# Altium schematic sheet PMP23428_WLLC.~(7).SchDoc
size 431 x 279 mm; Date: Not shown in title block; ApprovedBy: Not shown in title block; CheckedBy: Not shown in title block; Author: Not shown in title block; CompanyName: Not shown in title block; Engineer: Not shown in title block; Organization: Not shown in title block; Address1: Not shown in title block; Address2: Not shown in title block; Address3: Not shown in title block; Address4: Not shown in title block; DocumentNumber: 1; Revision: Use project parameter SCH_Rev; SheetNumber: 3; SheetTotal: 4; PageSetup: Record=PageOptions¦CenterHorizontal=True¦CenterVertical=True¦PrintScale=1.00¦XCorrection=1.00¦YCorrection=1.00¦PrintKind=0¦BorderSize=5000000¦LeftOffset=0¦BottomOffset=0¦Orientation=2¦PaperLength=1000¦PaperWidth=1000¦Scale=100¦PaperSource=15¦PrintQuality=600¦MediaType=1¦DitherType=10¦PaperKind=Letter¦PrintScaleMode=1
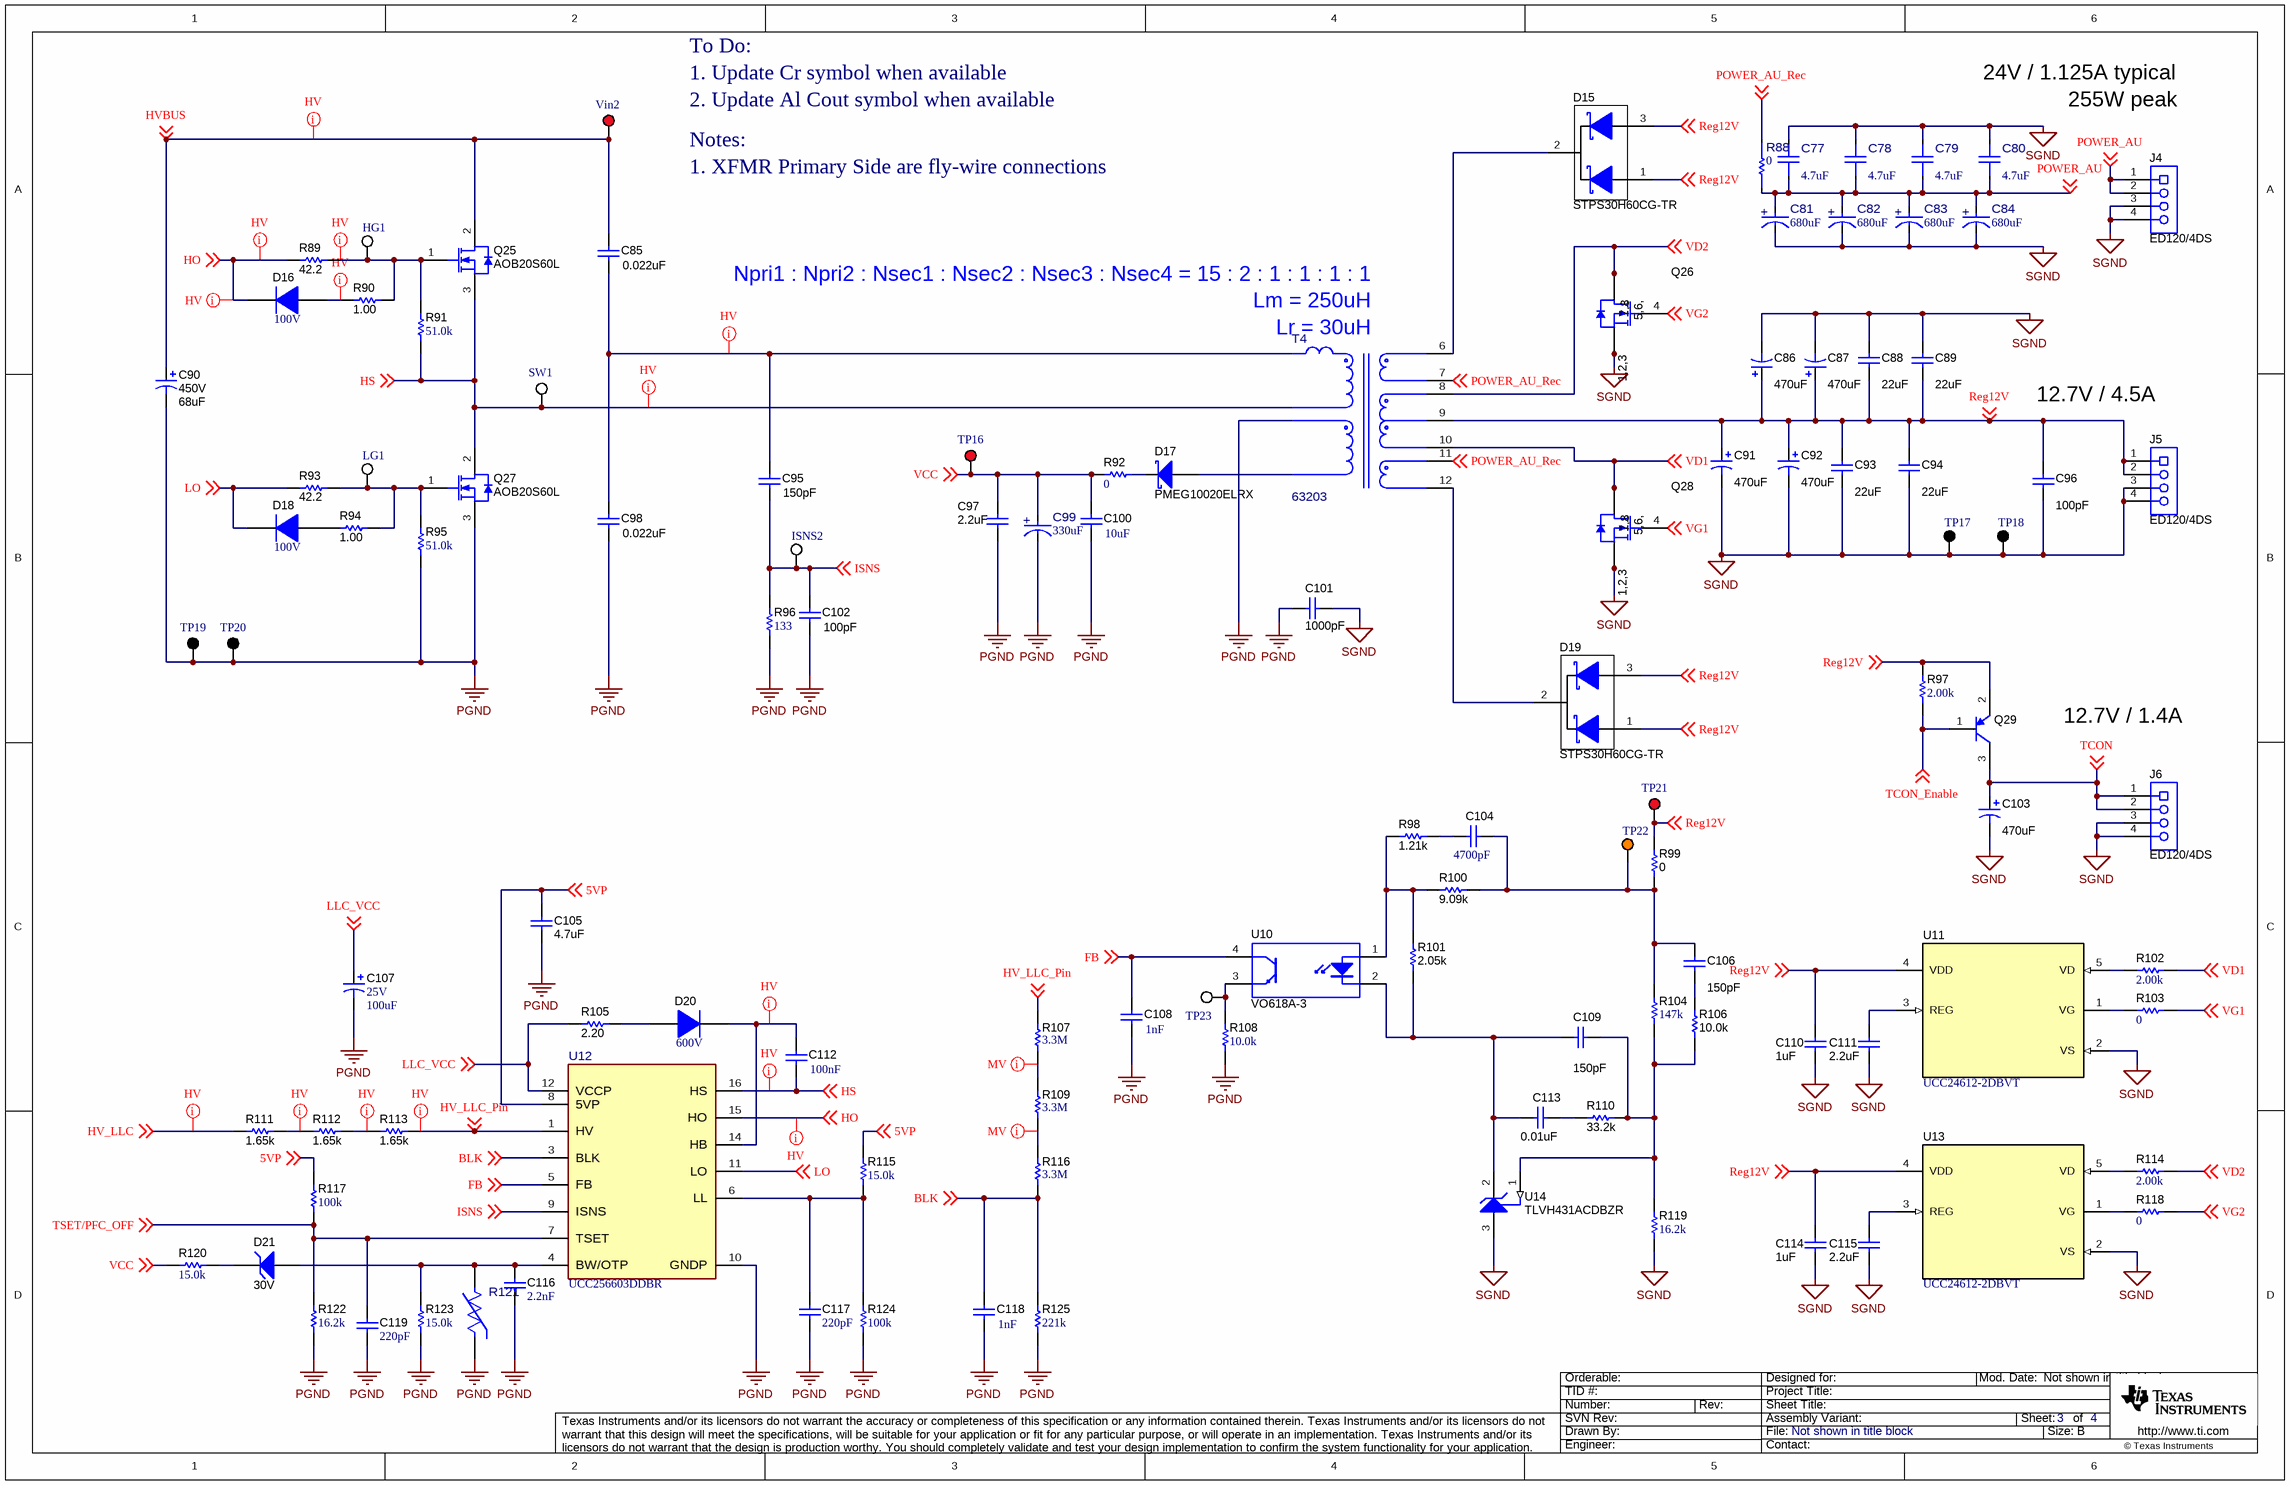
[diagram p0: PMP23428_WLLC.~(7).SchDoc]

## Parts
C77  ValueDisplayed: 4.7uF  [FP-885012208094_1206-MFG]  (hidden comment: 885012208094)
C78  ValueDisplayed: 4.7uF  [FP-885012208094_1206-MFG]  (hidden comment: 885012208094)
C79  ValueDisplayed: 4.7uF  [FP-885012208094_1206-MFG]  (hidden comment: 885012208094)
C80  ValueDisplayed: 4.7uF  [FP-885012208094_1206-MFG]  (hidden comment: 885012208094)
C81  ValueDisplayed: 680uF  [FP-EKZM350ELL681MJ25S_RADIAL-MFG]  (hidden comment: EKZM350ELL681MJ25S)
C82  ValueDisplayed: 680uF  [FP-EKZM350ELL681MJ25S_RADIAL-MFG]  (hidden comment: EKZM350ELL681MJ25S)
C83  ValueDisplayed: 680uF  [FP-EKZM350ELL681MJ25S_RADIAL-MFG]  (hidden comment: EKZM350ELL681MJ25S)
C84  ValueDisplayed: 680uF  [FP-EKZM350ELL681MJ25S_RADIAL-MFG]  (hidden comment: EKZM350ELL681MJ25S)
C85  ValueDisplayed: 0.022uF  [B32652_1800x700x1250]  (hidden comment: B32652A7153J000)
C86  ValueDisplayed: 470uF  [HW_1000x1600]  (hidden comment: UHW1V471MPD)
C87  ValueDisplayed: 470uF  [HW_1000x1600]  (hidden comment: UHW1V471MPD)
C88  ValueDisplayed: 22uF  [1206_190L]  (hidden comment: C3216X5R1E226M160AB)
C89  ValueDisplayed: 22uF  [1206_190L]  (hidden comment: C3216X5R1E226M160AB)
C90  VDC_V: 450V  ValueDisplayed: 68uF  [KXG_1800x3150]  (hidden comment: EKXG451ELL680MMN3S)
C91  ValueDisplayed: 470uF  [HW_1000x1600]  (hidden comment: UHW1V471MPD)
C92  ValueDisplayed: 470uF  [HW_1000x1600]  (hidden comment: UHW1V471MPD)
C93  ValueDisplayed: 22uF  [1206_190L]  (hidden comment: C3216X5R1E226M160AB)
C94  ValueDisplayed: 22uF  [1206_190L]  (hidden comment: C3216X5R1E226M160AB)
C95  ValueDisplayed: 150pF  [1206L]  (hidden comment: GRM31A5C2J151JW01D)
C96  ValueDisplayed: 100pF  [0603L]  (hidden comment: 06035A101FAT2A)
C97  ValueDisplayed: 2.2uF  [0805L]  (hidden comment: C2012X7R1V225K085AC)
C98  ValueDisplayed: 0.022uF  [B32652_1800x700x1250]  (hidden comment: B32652A7153J000)
C99  ValueDisplayed: 330uF  [FP-35ZL330MEFC10X16_RADIAL-MFG]  (hidden comment: 35ZL330MEFC10X16)
C100  ValueDisplayed: 10uF  [1210_270]  (hidden comment: GRM32ER6YA106KA12L)
C101  ValueDisplayed: 1000pF  [CD45_700x600x1100]  (hidden comment: CD45-E2GA102M-NKA)
C102  ValueDisplayed: 100pF  [1206L]  (hidden comment: 12061A101JAT2A)
C103  ValueDisplayed: 470uF  [HW_1000x1600]  (hidden comment: UHW1V471MPD)
C104  ValueDisplayed: 4700pF  [0603L]  (hidden comment: C0603C472J1GAC7867)
C105  ValueDisplayed: 4.7uF  [1206L]  (hidden comment: C3216X7R1E475K085AB)
C106  ValueDisplayed: 150pF  [0402L]  (hidden comment: 885012005062)
C107  VDC_V: 25V  ValueDisplayed: 100uF  [SM_RADIAL_E]  (hidden comment: EEE-FK1E101P)
C108  Cap_F: 1nF  [1206L]  (hidden comment: 12061A102JAT2A)
C109  ValueDisplayed: 150pF  [0402L]  (hidden comment: 885012005062)
C110  ValueDisplayed: 1uF  [0603L]  (hidden comment: GRM188R71C105KE15D)
C111  ValueDisplayed: 2.2uF  [0805L]  (hidden comment: C2012X7R1V225K085AC)
C112  Cap_F: 100nF  [1206_180L]  (hidden comment: GRM31C5C1E104JA01L)
C113  ValueDisplayed: 0.01uF  [0603L]  (hidden comment: 06031C103JAT2A)
C114  ValueDisplayed: 1uF  [0603L]  (hidden comment: GRM188R71C105KE15D)
C115  ValueDisplayed: 2.2uF  [0805L]  (hidden comment: C2012X7R1V225K085AC)
C116  Cap_F: 2.2nF  [0603]  (hidden comment: C0603X222K5RACTU)
C117  Cap_F: 220pF  [0603]  (hidden comment: C0603X221K5RACTU)
C118  Cap_F: 1nF  [0402L]  (hidden comment: 04025C102JAT2A)
C119  Cap_F: 220pF  [0603]  (hidden comment: C0603X221K5RACTU)
D15  STPS30H60CG-TR  [DDPAK]
D16  Vr_V: 100V  [SOD-123]  (hidden comment: 1N4148W-7-F)
D17  PMEG10020ELRX  [SOD-123W]
D18  Vr_V: 100V  [SOD-123]  (hidden comment: 1N4148W-7-F)
D19  STPS30H60CG-TR  [DDPAK]
D20  Vr_V: 600V  [SMAF]  (hidden comment: ES1JAF)
D21  value 30V  [SMA]  (hidden comment: SMAZ30-13-F)
HG1  5012  [Keystone5012]  (value not drawn)
ISNS2  5012  [Keystone5012]  (value not drawn)
J4  ED120/4DS  [On-Shore_ED120_4DS]
J5  ED120/4DS  [On-Shore_ED120_4DS]
J6  ED120/4DS  [On-Shore_ED120_4DS]
LG1  5012  [Keystone5012]  (value not drawn)
Q25  AOB20S60L  [DDPAK]
Q26  CSD19502Q5B  [DNK0008A]  (value not drawn)
Q27  AOB20S60L  [DDPAK]
Q28  CSD19502Q5B  [DNK0008A]  (value not drawn)
Q29  ZXTP25040DFHTA  [SOT-23]  (value not drawn)
R88  value 0  [FP-RMCF1206ZT0R00_1206-MFG]  (hidden comment: RMCF1206ZT0R00)
R89  ValueDisplayed: 42.2  [0603]  (hidden comment: RC0603FR-0742R2L)
R90  ValueDisplayed: 1.00  [0603L]  (hidden comment: RC0603FR-071RL)
R91  ValueDisplayed: 51.0k  [0603L]  (hidden comment: RC0603FR-0751KL)
R92  ValueDisplayed: 0  [1206L]  (hidden comment: ERJ-8GEY0R00V)
R93  ValueDisplayed: 42.2  [0603L]  (hidden comment: RC0603FR-0742R2L)
R94  ValueDisplayed: 1.00  [0603L]  (hidden comment: RC0603FR-071RL)
R95  ValueDisplayed: 51.0k  [0603L]  (hidden comment: RC0603FR-0751KL)
R96  ValueDisplayed: 133  [1206]  (hidden comment: RC1206FR-07133RL)
R97  ValueDisplayed: 2.00k  [0603]  (hidden comment: RC0603FR-072KL)
R98  ValueDisplayed: 1.21k  [0603L]  (hidden comment: RC0603FR-071K21L)
R99  ValueDisplayed: 0  [0402L]  (hidden comment: RC0402JR-070RL)
R100  ValueDisplayed: 9.09k  [0603L]  (hidden comment: RC0603FR-079K09L)
R101  ValueDisplayed: 2.05k  [0603L]  (hidden comment: RC0603FR-072K05L)
R102  ValueDisplayed: 2.00k  [0603]  (hidden comment: RC0603FR-072KL)
R103  ValueDisplayed: 0  [0603L]  (hidden comment: RC0603JR-070RL)
R104  ValueDisplayed: 147k  [0603L]  (hidden comment: RC0603FR-07147KL)
R105  ValueDisplayed: 2.20  [0603L]  (hidden comment: ERJ-3RQF2R2V)
R106  ValueDisplayed: 10.0k  [0603L]  (hidden comment: ERJ-3EKF1002V)
R107  Res_ohm: 3.3M  [FP-KTR18EZPF3304_1206-MFG]  (hidden comment: KTR18EZPF3304)
R108  ValueDisplayed: 10.0k  [0402L]  (hidden comment: ERJ-2RKF1002X)
R109  Res_ohm: 3.3M  [FP-KTR18EZPF3304_1206-MFG]  (hidden comment: KTR18EZPF3304)
R110  ValueDisplayed: 33.2k  [0603L]  (hidden comment: RC0603FR-0733K2L)
R111  ValueDisplayed: 1.65k  [1206L]  (hidden comment: CRCW12061K65FKEA)
R112  ValueDisplayed: 1.65k  [1206L]  (hidden comment: CRCW12061K65FKEA)
R113  ValueDisplayed: 1.65k  [1206L]  (hidden comment: CRCW12061K65FKEA)
R114  ValueDisplayed: 2.00k  [0603]  (hidden comment: RC0603FR-072KL)
R115  ValueDisplayed: 15.0k  [0603]  (hidden comment: RT0603BRD0715KL)
R116  Res_ohm: 3.3M  [FP-KTR18EZPF3304_1206-MFG]  (hidden comment: KTR18EZPF3304)
R117  ValueDisplayed: 100k  [0603]  (hidden comment: RC0603FR-07100KL)
R118  ValueDisplayed: 0  [0603L]  (hidden comment: RC0603JR-070RL)
R119  ValueDisplayed: 16.2k  [0603]  (hidden comment: RC0603FR-0716K2L)
R120  ValueDisplayed: 15.0k  [0603]  (hidden comment: RG1608P-153-B-T5)
R121  B57371V2474J060  [FP-B57371V2474J060_0603-MFG]  (value not drawn)
R122  ValueDisplayed: 16.2k  [0603]  (hidden comment: RC0603FR-0716K2L)
R123  ValueDisplayed: 15.0k  [0603]  (hidden comment: RG1608P-153-B-T5)
R124  ValueDisplayed: 100k  [0603]  (hidden comment: RT0603BRD07100KL)
R125  ValueDisplayed: 221k  [0603]  (hidden comment: RC0603FR-07221KL)
SW1  5012  [Keystone5012]  (value not drawn)
T4  63203  [FP-63203_W80MM0_H64MM0-MFG]
TP16  5010  [Keystone5010]  (value not drawn)
TP17  5011  [Keystone5011]  (value not drawn)
TP18  5011  [Keystone5011]  (value not drawn)
TP19  5011  [Keystone5011]  (value not drawn)
TP20  5011  [Keystone5011]  (value not drawn)
TP21  5010  [Keystone5010]  (value not drawn)
TP22  5013  [Keystone5013]  (value not drawn)
TP23  5012  [Keystone5012]  (value not drawn)
U10  VO618A-3  [DIP-4]
U11  UCC24612-2DBVT  [DBV0005A_N]
U12  UCC256603DDBR  [DDB0014A-MFG]
U13  UCC24612-2DBVT  [DBV0005A_N]
U14  TLVH431ACDBZR  [DBZ0003A_N]
Vin2  5010  [Keystone5010]  (value not drawn)

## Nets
PGND: C90.2(-) C97.2 C98.2 C99.1(CATHODE) C100.2 C101.2 C102.2 C105.2 C107.2(-) C108.2 C116.2 C117.2 C118.2 C119.2 Q27.3(S) R95.1 R96.1 R108.1 R121.1 R122.1 R123.1 R124.1 R125.1 TP19.1 TP20.1 U12.10(GNDP)
SGND: C77.2 C78.2 C79.2 C80.2 C81.1(CATHODE) C82.1(CATHODE) C83.1(CATHODE) C84.1(CATHODE) C86.2(-) C87.2(-) C88.1 C89.1 C91.2(-) C92.2(-) C93.2 C94.2 C96.2 C101.1 C103.2(-) C110.2 C111.2 C114.2 C115.2 J4.3 J4.4 J5.3 J5.4 J6.3 J6.4 Q26.1(S) Q26.2(S) Q26.3(S) Q28.1(S) Q28.2(S) Q28.3(S) R119.1 TP17.1 TP18.1 U11.2(VS) U13.2(VS) U14.3(ANODE)
5VP: C105.1 R115.2 R117.2 U12.8(5VP) ; off-sheet 5VP
BLK: C118.1 R116.1 R125.2 U12.3(BLK) ; off-sheet BLK
FB: C108.1 U10.4(C) U12.5(FB) ; off-sheet FB
HO: D16.1(K) R89.1 U12.15(HO) ; off-sheet HO
HS: C112.2 Q25.3(S) Q27.2(D) R91.1 SW1.1 U12.16(HS) ; off-sheet HS
HV_LLC: R111.1 ; off-sheet HV_LLC
HV_LLC_Pin: R107.2 R113.2 U12.1(HV) ; off-sheet HV_LLC_Pin
HVBUS: C85.1 C90.1(+) Q25.2(D) Vin2.1 ; off-sheet HVBUS
ISNS: C95.2 C102.1 ISNS2.1 R96.2 U12.9(ISNS) ; off-sheet ISNS
LLC_VCC: C107.1(+) R105.1 U12.12(VCCP) ; off-sheet LLC_VCC
LO: D18.1(K) R93.1 U12.11(LO) ; off-sheet LO
POWER_AU: C77.1 C78.1 C79.1 C80.1 C81.2(ANODE) C82.2(ANODE) C83.2(ANODE) C84.2(ANODE) J4.1 J4.2 R88.2 ; off-sheet POWER_AU
POWER_AU_Rec: R88.1 T4.7 T4.11 ; off-sheet POWER_AU_Rec
Reg12V: C86.1(+) C87.1(+) C88.2 C89.2 C91.1(+) C92.1(+) C93.1 C94.1 C96.1 C110.1 C114.1 D15.1(A) D15.3(A) D19.1(A) D19.3(A) J5.1 J5.2 Q29.2(E) R97.2 R99.2 T4.9 TP21.1 U11.4(VDD) U13.4(VDD) ; off-sheet Reg12V
TCON: C103.1(+) J6.1 J6.2 Q29.3(C) ; off-sheet TCON
TCON_Enable: Q29.1(B) R97.1 ; off-sheet TCON_Enable
TSET/PFC_OFF: C119.1 R117.1 R122.2 U12.7(TSET) ; off-sheet TSET/PFC_OFF
VCC: C97.1 C99.2(ANODE) C100.1 R92.1 R120.2 TP16.1 ; off-sheet VCC
VD1: Q28.5(D) Q28.6(D) Q28.7(D) Q28.8(D) Q28.9(D) R102.2 T4.10 ; off-sheet VD1
VD2: Q26.5(D) Q26.6(D) Q26.7(D) Q26.8(D) Q26.9(D) R114.2 T4.8 ; off-sheet VD2
VG1: Q28.4(G) R103.1 ; off-sheet VG1
VG2: Q26.4(G) R118.1 ; off-sheet VG2
NetC85_2: C85.2 C95.1 C98.1
NetC104_1: C104.1 C106.1 R99.1 R100.2 R104.2 TP22.1
NetC104_2: C104.2 R98.2
NetC106_2: C106.2 R106.2
NetC109_1: C109.1 R104.1 R106.1 R110.1 R119.2 U14.1(REF)
NetC109_2: C109.2 C113.2 R101.1 U10.2(K) U14.2(CATHODE)
NetC111_1: C111.1 U11.3(REG)
NetC112_1: C112.1 D20.1(K) U12.14(HB)
NetC113_1: C113.1 R110.2
NetC115_1: C115.1 U13.3(REG)
NetC116_1: C116.1 D21.2(A) R121.2 R123.2 U12.4(BW/OTP)
NetC117_1: C117.1 R115.1 R124.2 U12.6(LL)
NetD15_2: D15.2(K) T4.6
NetD16_2: D16.2(A) R90.1
NetD17_1: D17.1(K) R92.2
NetD18_2: D18.2(A) R94.1
NetD19_2: D19.2(K) T4.12
NetD20_2: D20.2(A) R105.2
NetD21_1: D21.1(K) R120.1
NetHG1_1: HG1.1 Q25.1(G) R89.2 R90.2 R91.2
NetLG1_1: LG1.1 Q27.1(G) R93.2 R94.2 R95.2
NetR98_1: R98.1 R100.1 R101.2 U10.1(A)
NetR102_1: R102.1 U11.5(VD)
NetR103_2: R103.2 U11.1(VG)
NetR107_1: R107.1 R109.2
NetR108_2: R108.2 TP23.1 U10.3(E)
NetR109_1: R109.1 R116.2
NetR111_2: R111.2 R112.1
NetR112_2: R112.2 R113.1
NetR114_1: R114.1 U13.5(VD)
NetR118_2: R118.2 U13.1(VG)

Not connected (* = marked no-connect by the designer): D17 2(A)

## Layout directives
net class HV: HO, HS, HV_LLC, HV_LLC_Pin, HVBUS, NetC85_2, NetC112_1, NetD16_2, NetHG1_1, NetR111_2, NetR112_2
net class MV: NetR107_1, NetR109_1

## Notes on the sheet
- To Do:
- 1. Update Cr symbol when available
- 255W peak
- 24V / 1.125A typical
- 2. Update Al Cout symbol when available
- Notes:
- 1. XFMR Primary Side are fly-wire connections
- Lm = 250uH
- (near C85) Npri1 : Npri2 : Nsec1 : Nsec2 : Nsec3 : Nsec4 = 15 : 2 : 1 : 1 : 1 : 1
- Lr = 30uH
- 12.7V / 4.5A
- 12.7V / 1.4A

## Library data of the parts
C77-C80 = CMP-0088282-2: 4.7µF ±10% 50V Ceramic Capacitor X7R 1206 (3216 Metric); Manufacturer: Wurth Electronics; TempCo: 15%; Symbol Name: SYM-885012208094; SizeZ_mm: 1.9mm; AEC Qualified: No
C81-C84 = CMP-0001423-1: Cap Aluminum Lytic 680uF 35V 20% (10 X 25mm) Radial 5mm 2250mA 10000h 105 Bulk; Manufacturer: United Chemi-Con; AEC Qualified: No; Cap_F: 680µF; IRMS_A: 2.25A; SizeZ_mm: 26.5mm; Dissipation Factor: 12%; Leakage Current: 238uA; Life: 10000Hours; Value: 680µF
C85 C98 = CMP-0012346-3: Manufacturer: TDK; TaMin_C: -55°C; Polarized: N; SizeAreaWB_mm2: 180; Value1: Unknown; Value: 0.015uF; TaMax_C: 100°C; Tolerance_%: 5%; SizeZ_mm: 12.5; SizeX_mm: 18; SizeY_mm: 7; Cap_Case: 18x7x12.5; Value2: 1250V; SizeArea_mm2: 126; CompType: Capacitor; AEC Qualified: Y; Cap_F: 15nF; VDC_V: 1.25kV; AEC Grade: 3; AEC Category: Q200
C86 C87 C91 C92 C103 = CMP-0010541-2: CAP, AL, 470 uF, 35 V, +/- 20%, 0.03 ohm, TH; Manufacturer: Nichicon; TaMin_C: -40°C; ESR_ohm: 0.03; Polarized: Y; SizeAreaWB_mm2: 144; U/M: EA; Value: 470uF; TaMax_C: 105°C; SizeZ_mm: 17.5; SizeX_mm: 10; Cap_Case: 10x16mm; Value2: 35V; SizeArea_mm2: 100; CompType: Capacitor; AEC Qualified: N; Cap_F: 470µF; IRMS_A: 2A; AEC Category: Q200
C88 C89 C93 C94 = CMP-0008654-2: CAP, CERM, 22 uF, 25 V, +/- 20%, X5R, 1206_190; Manufacturer: TDK; TaMin_C: -55°C; Polarized: N; SizeAreaWB_mm2: 10.92; Value1: Unknown; U/M: EA; Value: 22uF; TaMax_C: 85°C; SizeZ_mm: 1.9; SizeX_mm: 3.2; SizeY_mm: 1.6; Cap_Case: 1206; Value2: 25V; SizeArea_mm2: 5.12; CompType: Capacitor; Cap_F: 22µF; AEC Category: Q200
C90 = CMP-0010043-2: CAP, AL, 68 uF, 450 V, +/- 20%, TH; Manufacturer: Chemi-Con; TaMin_C: -25°C; Polarized: Y; SizeAreaWB_mm2: 400; Value1: Unknown; U/M: EA; Value: 68uF; TaMax_C: 105°C; SizeZ_mm: 33; SizeX_mm: 18; Cap_Case: 18x31.5mm; SizeArea_mm2: 324; CompType: Capacitor; Cap_F: 68µF; IRMS_A: 6.3dA; AEC Category: Q200
C95 = CMP-0008885-2: CAP, CERM, 150 pF, 630 V, +/- 5%, C0G/NP0, 1206; Manufacturer: MuRata; TaMin_C: -55°C; Polarized: N; SizeAreaWB_mm2: 10.92; Value1: Unknown; U/M: EA; Value: 150pF; TaMax_C: 125°C; SizeZ_mm: 1.35; SizeX_mm: 3.2; SizeY_mm: 1.6; Cap_Case: 1206; Value2: 630V; SizeArea_mm2: 5.12; CompType: Capacitor; AEC Category: Q200
C96 = CMP-0006762-4: CAP, CERM, 100 pF, 50 V, +/- 1%, C0G/NP0, 0603; Manufacturer: AVX; TaMin_C: -55°C; Polarized: N; SizeAreaWB_mm2: 4.68; Value1: Unknown; U/M: EA; TaMax_C: 125°C; SizeZ_mm: 1; SizeX_mm: 1.6; SizeY_mm: 0.8; Cap_Case: 0603; Value2: 50V; SizeArea_mm2: 1.28; CompType: Capacitor; Value: 100pF; AEC Category: Q200
C97 C111 C115 = CMP-0007883-2: CAP, CERM, 2.2 uF, 35 V, +/- 10%, X7R, 0805; Manufacturer: TDK; TaMin_C: -55°C; Polarized: N; SizeAreaWB_mm2: 6.75; Value1: Unknown; U/M: EA; Value: 2.2uF; TaMax_C: 125°C; SizeZ_mm: 1.45; SizeX_mm: 2; SizeY_mm: 1.25; Cap_Case: 0805; Value2: 35V; SizeArea_mm2: 2.5; CompType: Capacitor; Cap_F: 2.2µF; AEC Category: Q200
C99 = CMP-0098283-1: Cap Aluminum Lytic 330uF 35V 20% (10 X 16mm) Radial 5mm 1430mA 4000h 105C Bulk; Manufacturer: Rubycon; AEC Qualified: No; Cap_F: 330µF; IRMS_A: 1.43A; SizeZ_mm: 17.5mm; Dissipation Factor: 12%; Leakage Current: 115.5uA; Life: 4000Hours; Value: 330µF
C100 = CMP-0009215-2: CAP, CERM, 10 uF, 35 V, +/- 10%, X5R, 1210; Manufacturer: MuRata; TaMin_C: -55°C; Polarized: N; SizeAreaWB_mm2: 14.7; Value1: Unknown; U/M: EA; Value: 10uF; TaMax_C: 85°C; SizeZ_mm: 2.7; SizeX_mm: 3.2; SizeY_mm: 2.5; Cap_Case: 1210; Value2: 35V; SizeArea_mm2: 8; Cap_F: 10µF; AEC Category: Q200
C101 = CMP-0009595-2: CAP, CERM, 1000 pF,  V, +/- 20%, E, D7xT6mm; Manufacturer: TDK; TaMin_C: -25°C; Polarized: N; SizeAreaWB_mm2: 101.2; Value1: Unknown; U/M: EA; Value: 1000pF; TaMax_C: 125°C; SizeZ_mm: 11; SizeX_mm: 10.65; SizeY_mm: 6; Cap_Case: 7x6x11mm; SizeArea_mm2: 63.9; Cap_F: 1nF; AEC Category: Q200
C102 = CMP-0008462-2: CAP, CERM, 100 pF, 100 V, +/- 5%, C0G/NP0, 1206; Manufacturer: AVX; TaMin_C: -55°C; ESR_ohm: 7.01d; Polarized: N; SizeAreaWB_mm2: 10.92; Value1: 0.701 ohm; U/M: EA; Value: 100pF; TaMax_C: 125°C; SizeZ_mm: 1.35; SizeX_mm: 3.2; SizeY_mm: 1.6; Cap_Case: 1206; Value2: 100V; SizeArea_mm2: 5.12; CompType: Capacitor; AEC Category: Q200
C104 = CMP-0006941-4: CAP, CERM, 4700 pF, 100 V, +/- 5%, C0G/NP0, 0603; Manufacturer: Kemet; TaMin_C: -55°C; Polarized: N; SizeAreaWB_mm2: 4.68; Value1: Unknown; U/M: EA; Value: 4700pF; TaMax_C: 125°C; SizeZ_mm: 1; SizeX_mm: 1.6; SizeY_mm: 0.8; Cap_Case: 0603; Value2: 100V; SizeArea_mm2: 1.28; Cap_F: 4.7nF; AEC Category: Q200
C105 = CMP-0008693-2: CAP, CERM, 4.7 uF, 25 V, +/- 10%, X7R, 1206; Manufacturer: TDK; TaMin_C: -55°C; Polarized: N; SizeAreaWB_mm2: 10.92; Value1: Unknown; U/M: EA; Value: 4.7uF; TaMax_C: 125°C; SizeZ_mm: 1.35; SizeX_mm: 3.2; SizeY_mm: 1.6; Cap_Case: 1206; Value2: 25V; SizeArea_mm2: 5.12; CompType: Capacitor; Cap_F: 4.7µF; AEC Category: Q200
C106 C109 = CMP-0064913-2: CAP, CERM, 150 pF, 50 V,+/- 5%, C0G/NP0, 0402; Manufacturer: Wurth Elektronik; TaMin_C: -55°C; Polarized: N; SizeAreaWB_mm2: 3; Value1: Unknown; U/M: EA; Value: 150pF; TaMax_C: 125°C; SizeZ_mm: 0.6; SizeX_mm: 1; SizeY_mm: 0.5; Cap_Case: 0402; Value2: 50V; CompType: Capacitor; AEC Category: Q200
C107 = CMP-0010710-1: CAP, AL, 100 uF, 25 V, +/- 20%, 0.26 ohm, AEC-Q200 Grade 2, SMD; Manufacturer: Panasonic; TaMin_C: -55°C; ESR_ohm: 2.6d; Polarized: Y; SizeAreaWB_mm2: 118.45; U/M: EA; Value: 100uF; TaMax_C: 105°C; SizeZ_mm: 6.2; SizeX_mm: 9.5; SizeY_mm: 8.3; Cap_Case: E; SizeArea_mm2: 78.85; CompType: Capacitor; Cap_F: 100µF; IRMS_A: 3dA; AEC Grade: 2; AEC Category: Q200
C108 = CMP-0008465-2: CAP, CERM, 1000 pF, 100 V, +/- 5%, C0G/NP0, 1206; Manufacturer: AVX; TaMin_C: -55°C; ESR_ohm: 2.38d; Polarized: N; SizeAreaWB_mm2: 10.92; Value1: 0.238 ohm; U/M: EA; Value: 1000pF; TaMax_C: 125°C; SizeZ_mm: 1.35; SizeX_mm: 3.2; SizeY_mm: 1.6; Cap_Case: 1206; Value2: 100V; SizeArea_mm2: 5.12; AEC Category: Q200
C110 C114 = CMP-0007380-4: CAP, CERM, 1 uF, 16 V, +/- 10%, X7R, 0603; Manufacturer: MuRata; TaMin_C: -55°C; Polarized: N; SizeAreaWB_mm2: 4.68; Value1: Unknown; U/M: EA; Value: 1uF; TaMax_C: 125°C; SizeZ_mm: 1; SizeX_mm: 1.6; SizeY_mm: 0.8; Cap_Case: 0603; Value2: 16V; SizeArea_mm2: 1.28; CompType: Capacitor; Cap_F: 1µF; AEC Category: Q200
C112 = CMP-0064950-2: CAP, CERM, 0.1 uF, 25 V,+/- 5%, C0G/NP0, 1206; Manufacturer: MuRata; TaMin_C: -55°C; Polarized: N; SizeAreaWB_mm2: 10.92; Value1: Unknown; U/M: EA; Value: 0.1uF; TaMax_C: 125°C; SizeZ_mm: 1.8; SizeX_mm: 3.2; SizeY_mm: 1.6; Cap_Case: 1206; Value2: 25V; SizeArea_mm2: 5.12; AEC Category: Q200
C113 = CMP-0006726-4: CAP, CERM, 0.01 uF, 100 V, +/- 5%, X7R, 0603; Manufacturer: AVX; TaMin_C: -55°C; ESR_ohm: 0.098; Polarized: N; SizeAreaWB_mm2: 4.68; Value1: 0.098 ohm; U/M: EA; Value: 0.01uF; TaMax_C: 125°C; SizeZ_mm: 1; SizeX_mm: 1.6; SizeY_mm: 0.8; Cap_Case: 0603; Value2: 100V; SizeArea_mm2: 1.28; Cap_F: 10nF; AEC Category: Q200
C116 = CMP-0006983-4: CAP, CERM, 2200 pF, 50 V, +/- 10%, X7R, 0603; Manufacturer: Kemet; TaMin_C: -55°C; Polarized: N; SizeAreaWB_mm2: 4.68; Value1: Unknown; U/M: EA; Value: 2200pF; TaMax_C: 125°C; SizeZ_mm: 1; SizeX_mm: 1.6; SizeY_mm: 0.8; Value2: 50V; SizeArea_mm2: 1.28; AEC Category: Q200
C117 C119 = CMP-0006982-4: CAP, CERM, 220 pF, 50 V, +/- 10%, X7R, 0603; Manufacturer: Kemet; TaMin_C: -55°C; Polarized: N; SizeAreaWB_mm2: 4.68; Value1: Unknown; U/M: EA; Value: 220pF; TaMax_C: 125°C; SizeZ_mm: 1; SizeX_mm: 1.6; SizeY_mm: 0.8; Value2: 50V; SizeArea_mm2: 1.28; AEC Category: Q200
C118 = CMP-0861060-1: CAP, CERM, 1000 pF, 50 V,+/- 5%, X7R, 0402; Manufacturer: AVX; Value2: 50V; SizeY_mm: 0.5; AEC Category: Q200; Polarized: N; Green_Lifecycle: Active; SizeAreaWB_mm2: 3; ValueDisplayed: 1000pF; Cap_Case: 0402; Value: 1000pF; TaMin_C: -55°C; U/M: EA; Green_REACh: Passed; SizeZ_mm: 0.6; SizeX_mm: 1; TaMax_C: 125°C
D15 D19 = CMP-0077294-3: Diode, Schottky, 60 V, 15 A, TH; Manufacturer: STMicroelectronics; AEC Category: Q101; AEC Qualified: N; TJmax_C: 175°C; RJC_CperW: 0.8; SizeArea_mm2: 154.8892; Vr_V: 60V; SizeAreaWB_mm2: 209.6992; SizeX_mm: 15.245; Vf_V: 535mV; SizeY_mm: 10.16; Value1: 15A; Value2: 0.535V; SizeZ_mm: 4.445; Value: 60V
D16 D18 = CMP-0029001-2: Diode, Ultrafast, 100 V, 0.15 A, SOD-123; Manufacturer: Diodes Inc.; Io_A: 150mA; Green_Lifecycle: Active; SizeAreaWB_mm2: 13.095; Green_REACh: Passed; Value1: 0.15A; TJmax_C: 150°C; Value: 100V; SizeZ_mm: 1.35; SizeX_mm: 3.85; SizeY_mm: 1.7; Vf_V: 1.25V; SizeArea_mm2: 6.545; AEC Category: Q101
D17 = CMP-0028977-2: Diode, Schottky, 100 V, 2 A, AEC-Q101, SOD-123W; Manufacturer: Nexperia; Io_A: 2A; SizeAreaWB_mm2: 12.15; Vr_V: 100V; TJmax_C: 175°C; Value: 100V; SizeZ_mm: 1; SizeX_mm: 3.5; SizeY_mm: 1.7; Vf_V: 830mV; Value2: 0.83V; SizeArea_mm2: 5.95; AEC Qualified: Y; AEC Category: Q101
D20 = CMP-0029162-2: Diode, Ultrafast, 600 V, 1 A, AEC-Q101, SMAF; Manufacturer: Fairchild Semiconductor; Io_A: 1A; Green_Lifecycle: Not Set; SizeAreaWB_mm2: 19.95; Green_REACh: Incomplete; TJmax_C: 150°C; Value: 600V; SizeZ_mm: 1; SizeX_mm: 4.7; SizeY_mm: 2.5; Vf_V: 1.7V; SizeArea_mm2: 11.75; AEC Qualified: Y; AEC Category: Q101
D21 = CMP-0005528-5: Diode, Zener, 30 V, 1 W, SMA; Manufacturer: Diodes Inc.; Value1: 1W; SizeZ_mm: 2.87; RJA_CperW: 100; AEC Category: Q101; SizeArea_mm2: 16.3228; SizeX_mm: 5.59; SizeY_mm: 2.92; SizeAreaWB_mm2: 37.3428; AEC Qualified: N
HG1 ISNS2 LG1 SW1 TP23 = CMP-0055149-2: Test Point, Multipurpose, White, TH; Manufacturer: Keystone Electronics; CNHeader: FALSE; Green_Lifecycle: Active; Green_REACh: Passed; ContactFinish: Silver; CT: TRUE
J4-J6 = CMP-0074939-1: Terminal Block, 5.08 mm, 4x1, Brass, TH; Manufacturer: On-Shore Technology; Cert_VDE: Y; CNHeader: False; Current_A: 15A; Green_Lifecycle: Not Set; Shrouded: N; Gender: Female; Green_REACh: Incomplete; Voltage_V: 300V; Row_Count: 1; Pitch_mm: 5.08; CT: True
Q25 Q27 = CMP-0001135-4: MOSFET, N-CH, 600 V, 20 A, DDPAK; Alternate Manufacturer: None; Manufacturer: AOS; SizeZ_mm: 4.445; ChType: N; Value2: 19.8 nC; VdsMax_V: 600V; SizeX_mm: 15.245; SizeAreaWB_mm2: 209.6992; SizeY_mm: 10.16; Vgs_V: 30V; QgTyp_nC: 19.8; Value: 600V; SizeArea_mm2: 154.8892; AEC Category: Q101; IdsMax_A: 20A; ChMode: Enhancement
Q26 Q28 = CMP-0000915-2: MOSFET, N-CH, 80 V, 100 A, DNK0008A (VSON-CLIP-8); Alternate Manufacturer: None; Manufacturer: Texas Instruments; SizeZ_mm: 1; ChType: N; Value2: 48 nC; VdsMax_V: 80V; SizeX_mm: 6; SizeY_mm: 5; Vgs_V: 20V; Value: 80V; SizeArea_mm2: 30; AEC Category: Q101; IdsMax_A: 100A; SizeAreaWB_mm2: 56; U/M: EA; QgTyp_nC: 48
Q29 = CMP-0000353-2: Transistor, PNP, 40 V, 3 A, SOT-23; Manufacturer: Diodes Inc.; TaMax_C: 150°C; Value2: 900; Value1: 3 A; Vcesat1_V: 1.7dV; SizeX_mm: 2.5; SizeY_mm: 3; TaMin_C: -55°C; IcRated_A: 3A; CompType: BJT; SizeZ_mm: 1.1; AEC Qualified: N; Value: 40 V; SizeArea_mm2: 7.5; NPN: 0; Vceo_V: 40V; PNP: 1; AEC Category: Q101; SizeAreaWB_mm2: 14; U/M: EA
R88 = CMP-0093609-1: 0Ω ±0 0.25W 1206 Thick Film Chip Resistor AEC-Q200 compliant; Manufacturer: Stackpole Electronics; AEC Qualified: Yes; VDC_V: 200V; AEC Grade: Grade 0; Power_W: 250mW; SizeZ_mm: 0.7mm
R89 R93 = CMP-0023107-5: RES, 42.2, 1%, 0.1 W, 0603; Manufacturer: Yageo; Power_W: 100mW; TempCo: 100 ppm/C; Value_Code: 42R2; Value: 42.2; EIA_Code: E96; SizeX_mm: 1.6; SizeY_mm: 0.8; SizeZ_mm: 1; Value2: 0.1W; SizeArea_mm2: 1.28; CompType: Resistor; AEC Qualified: N; VDC_V: 75V; AEC Category: Q200; SizeAreaWB_mm2: 4.68
R90 R94 = CMP-0022900-4: RES, 1.00, 1%, 0.1 W, 0603; Manufacturer: Yageo; Power_W: 100mW; TempCo: 200 ppm/C; Value_Code: 1R00; Value: 1.00; EIA_Code: E96; Res_ohm: 1; SizeX_mm: 1.6; SizeY_mm: 0.8; Value2: 0.1W; SizeArea_mm2: 1.28; CompType: Resistor; AEC Qualified: N; VDC_V: 75V; AEC Category: Q200; SizeAreaWB_mm2: 4.68
R91 R95 = CMP-0023167-5: RES, 51.0 k, 1%, 0.1 W, 0603; Manufacturer: Yageo; Power_W: 100mW; TempCo: 100 ppm/C; Value_Code: 51k0; Value: 51.0k; Res_ohm: 51k; SizeX_mm: 1.6; SizeY_mm: 0.8; SizeZ_mm: 1; Value2: 0.1W; SizeArea_mm2: 1.28; AEC Qualified: N; VDC_V: 75V; AEC Category: Q200; SizeAreaWB_mm2: 4.68
R92 = CMP-0018748-3: RES, 0, 5%, 0.25 W, AEC-Q200 Grade 0, 1206; Manufacturer: Panasonic; Power_W: 250mW; TempCo: 600 ppm/C; Value_Code: 0000; Value: 0; EIA_Code: E24; SizeX_mm: 3.2; SizeY_mm: 1.6; SizeZ_mm: 1.35; Value2: 0.25W; SizeArea_mm2: 5.12; AEC Qualified: Y; VDC_V: 200V; AEC Category: Q200; SizeAreaWB_mm2: 10.92
R96 = CMP-0017887-2: RES, 133, 1%, 0.25 W, 1206; Manufacturer: Yageo America; Power_W: 250mW; TempCo: 100 ppm/C; Value_Code: 133R; U/M: EA; Value: 133; EIA_Code: E96; SizeX_mm: 3.2; SizeY_mm: 1.6; SizeZ_mm: 1.35; Value2: 0.25W; SizeArea_mm2: 5.12; VDC_V: 200V; AEC Category: Q200
R97 R102 R114 = CMP-0023000-5: RES, 2.00 k, 1%, 0.1 W, 0603; Manufacturer: Yageo; Power_W: 100mW; TempCo: 100 ppm/C; Value_Code: 2k00; Value: 2.00k; EIA_Code: E96; Res_ohm: 2k; SizeX_mm: 1.6; SizeY_mm: 0.8; SizeZ_mm: 1; Value2: 0.1W; SizeArea_mm2: 1.28; AEC Qualified: N; VDC_V: 75V; AEC Category: Q200; SizeAreaWB_mm2: 4.68
R98 = CMP-0022871-5: RES, 1.21 k, 1%, 0.1 W, 0603; Manufacturer: Yageo; Power_W: 100mW; TempCo: 100 ppm/C; Value_Code: 1k21; Value: 1.21k; EIA_Code: E96; SizeX_mm: 1.6; SizeY_mm: 0.8; SizeZ_mm: 1; Value2: 0.1W; SizeArea_mm2: 1.28; AEC Qualified: N; VDC_V: 75V; AEC Category: Q200; SizeAreaWB_mm2: 4.68
R99 = CMP-0027004-2: RES, 0, 5%, 0.063 W, 0402; Manufacturer: Yageo America; Power_W: 63mW; TempCo: 200 ppm/C; Value_Code: 0000; U/M: EA; Value: 0; EIA_Code: E24; SizeX_mm: 1; SizeY_mm: 0.5; SizeZ_mm: 0.6; Value2: 0.063W; CompType: Resistor; VDC_V: 50V; AEC Category: Q200
R100 = CMP-0023332-5: RES, 9.09 k, 1%, 0.1 W, 0603; Manufacturer: Yageo; Power_W: 100mW; TempCo: 100 ppm/C; Value_Code: 9k09; Value: 9.09k; EIA_Code: E96; SizeX_mm: 1.6; SizeY_mm: 0.8; SizeZ_mm: 1; Value2: 0.1W; SizeArea_mm2: 1.28; AEC Qualified: N; VDC_V: 75V; AEC Category: Q200; SizeAreaWB_mm2: 4.68
R101 = CMP-0022981-5: RES, 2.05 k, 1%, 0.1 W, 0603; Manufacturer: Yageo; Power_W: 100mW; TempCo: 100 ppm/C; Value_Code: 2k05; Value: 2.05k; EIA_Code: E96; SizeX_mm: 1.6; SizeY_mm: 0.8; SizeZ_mm: 1; Value2: 0.1W; SizeArea_mm2: 1.28; AEC Qualified: N; VDC_V: 75V; AEC Category: Q200; SizeAreaWB_mm2: 4.68
R103 R118 = CMP-0025885-5: RES, 0, 5%, 0.1 W, 0603; Manufacturer: Yageo; Power_W: 100mW; TempCo: 200 ppm/C; Value_Code: 0000; Value: 0; EIA_Code: E24; SizeX_mm: 1.6; SizeZ_mm: 1; Value2: 0.1W; SizeArea_mm2: 1.28; AEC Qualified: N; VDC_V: 75V; AEC Category: Q200; SizeY_mm: 0.8; SizeAreaWB_mm2: 4.68
R104 = CMP-0022800-4: RES, 147 k, 1%, 0.1 W, 0603; Manufacturer: Yageo; Power_W: 100mW; TempCo: 100 ppm/C; Value: 147k; EIA_Code: E96; SizeX_mm: 1.6; SizeY_mm: 0.8; SizeZ_mm: 1; Value2: 0.1W; SizeArea_mm2: 1.28; AEC Qualified: N; VDC_V: 75V; AEC Category: Q200; SizeAreaWB_mm2: 4.68
R105 = CMP-0022711-2: RES, 2.20, 1%, 0.1 W, 0603; Manufacturer: Panasonic; Power_W: 100mW; TempCo: 200 ppm/C; Value_Code: 2R20; U/M: EA; Value: 2.20; Res_ohm: 2.2; SizeX_mm: 1.6; SizeY_mm: 0.8; SizeZ_mm: 1; Value2: 0.1W; SizeArea_mm2: 1.28; CompType: Resistor; AEC Category: Q200
R106 = CMP-0022684-3: RES, 10.0 k, 1%, 0.1 W, 0603; Manufacturer: Panasonic; Power_W: 100mW; TempCo: 100 ppm/C; Value_Code: 10k0; U/M: EA; Value: 10.0k; EIA_Code: E96; Res_ohm: 10k; SizeX_mm: 1.6; SizeY_mm: 0.8; SizeZ_mm: 1; Value2: 0.1W; SizeArea_mm2: 1.28; CompType: Resistor; VDC_V: 75V; AEC Category: Q200
R107 R109 R116 = CMP-0087456-2: 3.3 MOhms ±1% 0.25W, 1/4W Chip Resistor 1206 (3216 Metric) Automotive AEC-Q200, High Voltage Thick Film; Manufacturer: Rohm Semiconductor; AEC Qualified: Yes; Power_W: 250mW; SizeZ_mm: 0.65mm; AEC Grade: Grade 0; TempCo: 100ppm/°C; VDC_V: 500V
R108 = CMP-0026658-1: RES, 10.0 k, 1%, 0.1 W, 0402; Manufacturer: Panasonic; Power_W: 100mW; TempCo: 100 ppm/C; Value_Code: 10k0; U/M: EA; Value: 10.0k; EIA_Code: E96; Res_ohm: 10k; SizeX_mm: 1; SizeY_mm: 0.5; SizeZ_mm: 0.6; Value2: 0.1W; VDC_V: 50V; AEC Category: Q200
R110 = CMP-0023036-5: RES, 33.2 k, 1%, 0.1 W, 0603; Manufacturer: Yageo; Power_W: 100mW; TempCo: 100 ppm/C; Value_Code: 33k2; Value: 33.2k; EIA_Code: E96; SizeX_mm: 1.6; SizeY_mm: 0.8; SizeZ_mm: 1; Value2: 0.1W; SizeArea_mm2: 1.28; AEC Qualified: N; VDC_V: 75V; AEC Category: Q200; SizeAreaWB_mm2: 4.68
R111-R113 = CMP-0016708-3: RES, 1.65 k, 1%, 0.25 W, AEC-Q200 Grade 0, 1206; Manufacturer: Vishay-Dale; Power_W: 250mW; TempCo: 100 ppm/C; Value_Code: 1k65; Value: 1.65k; EIA_Code: E96; SizeX_mm: 3.2; SizeY_mm: 1.6; SizeZ_mm: 1.35; Value2: 0.25W; SizeArea_mm2: 5.12; CompType: Resistor; AEC Qualified: Y; VDC_V: 200V; AEC Category: Q200; AEC Grade: 0
R115 = CMP-0023780-3: RES, 15.0 k, 0.1%, 0.1 W, 0603; Manufacturer: Yageo America; Power_W: 100mW; TempCo: 25 ppm/C; Value_Code: 15k0; U/M: EA; Value: 15.0k; EIA_Code: E192; Res_ohm: 15k; SizeX_mm: 1.6; SizeY_mm: 0.8; SizeZ_mm: 1; Value2: 0.1W; SizeArea_mm2: 1.28; VDC_V: 75V; AEC Category: Q200
R117 = CMP-0022735-5: RES, 100 k, 1%, 0.1 W, 0603; Manufacturer: Yageo; Power_W: 100mW; TempCo: 100 ppm/C; Value: 100k; EIA_Code: E96; SizeX_mm: 1.6; SizeY_mm: 0.8; SizeZ_mm: 1; Value2: 0.1W; SizeArea_mm2: 1.28; AEC Qualified: N; VDC_V: 75V; AEC Category: Q200; SizeAreaWB_mm2: 4.68
R119 R122 = CMP-0022828-5: RES, 16.2 k, 1%, 0.1 W, 0603; Manufacturer: Yageo; Power_W: 100mW; TempCo: 100 ppm/C; Value_Code: 16k2; Value: 16.2k; EIA_Code: E96; SizeX_mm: 1.6; SizeY_mm: 0.8; SizeZ_mm: 1; Value2: 0.1W; SizeArea_mm2: 1.28; AEC Qualified: N; VDC_V: 75V; AEC Category: Q200; SizeAreaWB_mm2: 4.68
R120 R123 = CMP-0023441-3: RES, 15.0 k, 0.1%, 0.1 W, 0603; Manufacturer: Susumu Co Ltd; Power_W: 100mW; TempCo: 25 ppm/C; Value_Code: 15k0; U/M: EA; Value: 15.0k; EIA_Code: E192; Res_ohm: 15k; SizeX_mm: 1.6; SizeY_mm: 0.8; SizeZ_mm: 1; Value2: 0.1W; SizeArea_mm2: 1.28; VDC_V: 75V; AEC Category: Q200
R121 = CMP-0096703-1: NTC Thermistor 470k 0603 (1608 Metric); Manufacturer: TDK; AEC Qualified: No; Res_ohm: 470kΩ; Power_W: 180mW; B 25 50: 4386K; B 25 100: 4480K; SizeZ_mm: 0.9mm; B 25 85: 4455K; B Tolerance: 3%; Tolerance_%: 5%
R124 = CMP-0023630-3: RES, 100 k, 0.1%, 0.1 W, 0603; Manufacturer: Yageo America; Power_W: 100mW; TempCo: 25 ppm/C; U/M: EA; Value: 100k; EIA_Code: E192; SizeX_mm: 1.6; SizeY_mm: 0.8; SizeZ_mm: 1; Value2: 0.1W; SizeArea_mm2: 1.28; VDC_V: 75V; AEC Category: Q200
R125 = CMP-0022919-4: RES, 221 k, 1%, 0.1 W, 0603; Manufacturer: Yageo; Power_W: 100mW; TempCo: 100 ppm/C; Value: 221k; EIA_Code: E96; SizeX_mm: 1.6; SizeY_mm: 0.8; SizeZ_mm: 1; Value2: 0.1W; SizeArea_mm2: 1.28; AEC Qualified: N; VDC_V: 75V; AEC Category: Q200; SizeAreaWB_mm2: 4.68
T4 = CMP-0120309-1: Transformer; Manufacturer: Payton Planar; Ind_H: 250µH; Ns1toNp: 15:2; SizeZ_mm: 10mm; AEC Qualified: No; Frequency_Fixed: 70-160kHz; TaMax_C: +30°C; TaMin_C: -40°C; Voltage_Isolation_Vrms: 2500VDC
TP16 TP21 Vin2 = CMP-0055147-2: Test Point, Multipurpose, Red, TH; Manufacturer: Keystone Electronics; CNHeader: FALSE; Green_Lifecycle: Active; Green_REACh: Passed; ContactFinish: Silver; CT: TRUE
TP17 TP18 = CMP-0055148-2: Test Point, Multipurpose, Black, TH; Manufacturer: Keystone Electronics; CNHeader: FALSE; ContactFinish: Silver; Green_REACh: Passed; Green_Lifecycle: Active; CT: TRUE
TP19 TP20 = CMP-0055148-2: Test Point, Multipurpose, Black, TH; Manufacturer: Keystone Electronics; CNHeader: FALSE; Green_Lifecycle: Active; Green_REACh: Passed; ContactFinish: Silver; CT: TRUE
TP22 = CMP-0055150-2: Test Point, Multipurpose, Orange, TH; Manufacturer: Keystone Electronics; CNHeader: FALSE; Green_Lifecycle: Active; Green_REACh: Passed; ContactFinish: Silver; CT: TRUE
U10 = CMP-0083653-1: Optocoupler, 5.3 kV, 100-200% CTR, SMT; Manufacturer: Vishay-Semiconductor; CTR (Max): 200%; SizeAreaWB_mm2: 71.064; CTR (Min): 100%; SizeZ_mm: 5; SizeX_mm: 8.8; SizeY_mm: 4.58; SizeArea_mm2: 40.304; Voltage_Isolation_Vrms: 5.3kV
U11 U13 = CMP-0013047-3: High-Frequency Multi-Mode Synchronous Rectifier Controller, DBV0005A (SOT-23-5); Manufacturer: Texas Instruments; Alternate PartNumber: UCC24612-2DBVR; SizeX_mm: 2.8; SizeY_mm: 2.9; CompType: IC; SizeZ_mm: 1.45; SizeArea_mm2: 8.12; SizeAreaWB_mm2: 14.82; AEC Category: Q200; AEC Qualified: N
U12 = CMP-0095299-1: 750kHz Wide VIN/VOUT Range LLC Controller Optimized for Light Load Efficiency; Manufacturer: Texas Instruments; Number Of Outputs: 2; TaMax_C: +125°C; Output Type: Other; TJmax_C: +150°C; AEC Qualified: No; Standoff Height: 0.1mm; TaMin_C: -40°C; SizeZ_mm: 1.75mm; Switching Frequency: 30-750kHz; Max Supply Voltage: 18.5V
U14 = CMP-0033066-1: Low-Voltage Adjustable Precision Shunt Regulator, 129 ppm / degC, 80 mA, 0 to 70 degC, 3-pin SOT-23 (DBZ), Green (RoHS & no Sb/Br); Manufacturer: Texas Instruments; Min Iz for Regulation(uA): 80; VO Adj(Max)(V): 18; VO Adj(Min)(V): 1.24; Rating: Catalog; SubFamily: Shunt Voltage Reference; Temp Coeff(Max)(ppm/ degree C): 129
